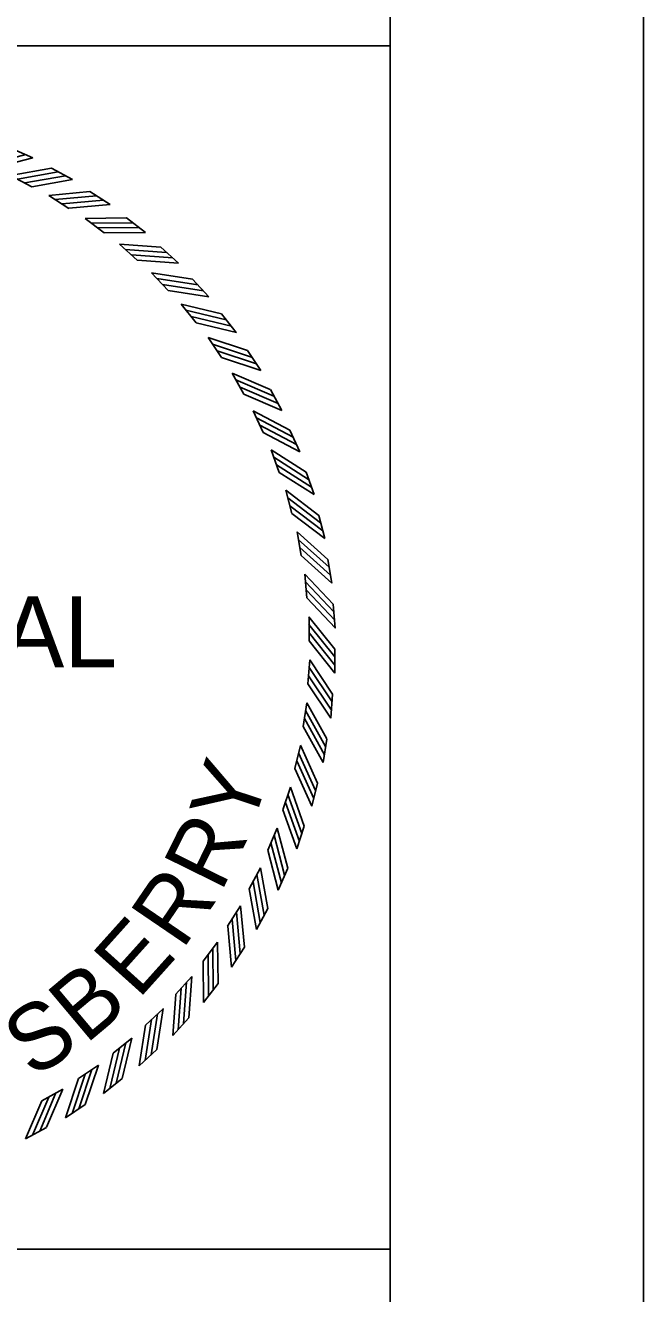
# Model space of a CAD drawing. Extents: x 0 to 1228740, y 0 to 152440.
# Drawn here: x 32.593 to 34, y 17.304 to 20.19 of the extents above; entities that cross this region are included whole.
import ezdxf

# ---------------------------------------------------------------- set-up
doc = ezdxf.new("R2010")
doc.units = 0
for name, color, linetype in [('R_Border', 7, 'Continuous'), ('R_No Plot', 7, 'Continuous'), ('STAMP_PP', 7, 'Continuous')]:
    doc.layers.add(name, color=color, linetype=linetype)

msp = doc.modelspace()

# ---------------------------------------------------------------- linework, layer by layer
at = {"layer": 'R_Border'}
for p, q in [((33.4231, 0.5768), (33.4231, 21.4232)), ((29.1131, 20.1432), (33.4231, 20.1432))]:
    msp.add_line(p, q, dxfattribs=at)
msp.add_lwpolyline([(33.9999, 22), (0, 22), (0, 0), (33.9999, 0)], close=True, dxfattribs=at)
at = {"layer": 'R_No Plot'}
for points in [[(33.4231, 17.4052), (33.4231, 0.5768), (1.516, 0.5768), (1.516, 21.4232), (20.2672, 21.4232), (20.2672, 20.4352), (28.7566, 20.4351), (28.7566, 20.0873), (29.1132, 20.0873), (29.1131, 20.1432), (30.6665, 20.1432)], [(30.6665, 20.1432), (30.6665, 17.4052), (33.4231, 17.4052)]]:
    msp.add_lwpolyline(points, dxfattribs=at)
msp.add_lwpolyline([(20.2672, 21.4232), (1.516, 21.4232), (1.516, 10.8708), (33.4231, 10.8708), (33.4231, 17.4052), (30.6665, 17.4052), (30.6665, 20.1432), (29.1132, 20.1432), (29.1132, 20.0873), (28.7566, 20.0873), (28.7566, 20.4351), (20.2672, 20.4351)], close=True, dxfattribs=at)
at = {"layer": 'STAMP_PP'}
for p, q in [((32.5606, 19.9103), (32.6107, 19.8889)), ((32.6526, 19.8648), (32.7006, 19.8393)), ((32.5598, 19.8484), (32.608, 19.8229)), ((32.6466, 19.8031), (32.6926, 19.7737)), ((32.7404, 19.8119), (32.7862, 19.7825)), ((32.7294, 19.7509), (32.7727, 19.7178)), ((32.8235, 19.7518), (32.8668, 19.7188)), ((32.8076, 19.692), (32.848, 19.6554)), ((32.9015, 19.6851), (32.9418, 19.6487)), ((32.8806, 19.6268), (32.9179, 19.587)), ((32.9736, 19.6123), (33.0108, 19.5726)), ((32.948, 19.5558), (32.9819, 19.5131)), ((33.0395, 19.5337), (33.0733, 19.491)), ((33.0093, 19.4796), (33.0396, 19.4342)), ((33.0987, 19.4499), (33.1288, 19.4046)), ((33.0641, 19.3985), (33.0905, 19.3507)), ((33.1507, 19.3615), (33.1771, 19.3139)), ((33.112, 19.3131), (33.1344, 19.2634)), ((33.1953, 19.2692), (33.2176, 19.2195)), ((33.1528, 19.2241), (33.1709, 19.1727)), ((33.2321, 19.1734), (33.2502, 19.1221)), ((33.186, 19.1321), (33.1998, 19.0793)), ((33.2608, 19.075), (33.2747, 19.0224)), ((33.2115, 19.0376), (33.2209, 18.9839)), ((33.2814, 18.9745), (33.2908, 18.9209)), ((33.2291, 18.9413), (33.2341, 18.887)), ((33.2936, 18.8727), (33.2985, 18.8185)), ((33.2387, 18.8439), (33.2392, 18.7893)), ((33.2973, 18.7702), (33.2978, 18.7158)), ((33.2402, 18.746), (33.2362, 18.6916)), ((33.2337, 18.6484), (33.2252, 18.5945)), ((33.2925, 18.6677), (33.2885, 18.6135)), ((33.2793, 18.566), (33.2708, 18.5123)), ((33.2191, 18.5516), (33.2062, 18.4986)), ((33.1965, 18.4563), (33.1793, 18.4046)), ((33.2577, 18.4657), (33.2449, 18.4129)), ((33.1662, 18.3633), (33.1447, 18.3131)), ((33.228, 18.3676), (33.2108, 18.316)), ((33.1283, 18.273), (33.1027, 18.2248)), ((33.1902, 18.2722), (33.1688, 18.2222)), ((33.083, 18.1863), (33.0536, 18.1403)), ((33.1447, 18.1803), (33.1192, 18.1323)), ((33.0308, 18.1035), (32.9977, 18.0601)), ((33.0917, 18.0925), (33.0624, 18.0467)), ((32.9719, 18.0253), (32.9353, 17.9849)), ((33.0317, 18.0093), (32.9987, 17.9661)), ((32.9067, 17.9523), (32.8669, 17.915)), ((32.965, 17.9314), (32.9286, 17.8911)), ((32.8357, 17.8849), (32.793, 17.851)), ((32.8922, 17.8593), (32.8525, 17.8221)), ((32.7595, 17.8236), (32.7141, 17.7933)), ((32.8136, 17.7934), (32.7709, 17.7596)), ((32.6784, 17.7688), (32.6306, 17.7424)), ((32.7298, 17.7342), (32.6845, 17.704)), ((32.6414, 17.6822), (32.5938, 17.6558))]:
    msp.add_line(p, q, dxfattribs=at)
for points in [[(32.5031, 19.8722), (32.5941, 19.8962)], [(32.5197, 19.8649), (32.6107, 19.8889)], [(32.5598, 19.8483), (32.6525, 19.8648)], [(32.5752, 19.84), (32.6679, 19.8565)], [(32.5921, 19.8315), (32.6848, 19.848)], [(32.608, 19.8229), (32.7007, 19.8394)], [(32.6466, 19.8031), (32.7403, 19.8119)], [(32.6612, 19.7935), (32.755, 19.8023)], [(32.6774, 19.7837), (32.7711, 19.7924)], [(32.6925, 19.7738), (32.7863, 19.7825)], [(32.7293, 19.7509), (32.8235, 19.7518)], [(32.7431, 19.7401), (32.8373, 19.7411)], [(32.7584, 19.729), (32.8526, 19.7299)], [(32.7727, 19.7179), (32.8669, 19.7188)], [(32.8075, 19.692), (32.9014, 19.6852)], [(32.8204, 19.6801), (32.9143, 19.6733)], [(32.8347, 19.6678), (32.9286, 19.6609)], [(32.848, 19.6555), (32.9419, 19.6487)], [(32.8805, 19.6268), (32.9735, 19.6123)], [(32.8924, 19.6139), (32.9854, 19.5994)], [(32.9056, 19.6004), (32.9986, 19.5859)], [(32.9179, 19.5871), (33.0109, 19.5726)], [(32.9479, 19.5559), (33.0394, 19.5337)], [(32.9587, 19.542), (33.0502, 19.5199)], [(32.9708, 19.5275), (33.0622, 19.5053)], [(32.9819, 19.5132), (33.0734, 19.491)], [(33.0092, 19.4796), (33.0986, 19.4499)], [(33.0188, 19.4649), (33.1082, 19.4353)], [(33.0296, 19.4494), (33.119, 19.4198)], [(33.0396, 19.4343), (33.1289, 19.4046)], [(33.064, 19.3985), (33.1506, 19.3616)], [(33.0724, 19.3831), (33.159, 19.3462)], [(33.0819, 19.3668), (33.1685, 19.3298)], [(33.0905, 19.3508), (33.1771, 19.3139)], [(33.112, 19.3132), (33.1952, 19.2692)], [(33.119, 19.2971), (33.2023, 19.2532)], [(33.1271, 19.2801), (33.2104, 19.2361)], [(33.1344, 19.2635), (33.2177, 19.2195)], [(33.1527, 19.2242), (33.232, 19.1735)], [(33.1584, 19.2076), (33.2377, 19.1569)], [(33.1651, 19.1899), (33.2444, 19.1392)], [(33.1709, 19.1728), (33.2503, 19.1221)], [(33.1859, 19.1321), (33.2608, 19.075)], [(33.1902, 19.1151), (33.2651, 19.0581)], [(33.1954, 19.097), (33.2703, 19.0399)], [(33.1999, 19.0794), (33.2747, 19.0223)], [(33.2114, 19.0376), (33.2813, 18.9746)], [(33.2143, 19.0203), (33.2842, 18.9573)], [(33.218, 19.0018), (33.2879, 18.9387)], [(33.221, 18.9839), (33.2909, 18.9209)], [(33.229, 18.9413), (33.2935, 18.8727)], [(33.2305, 18.9239), (33.2949, 18.8553)], [(33.2326, 18.9051), (33.2971, 18.8365)], [(33.2341, 18.887), (33.2986, 18.8184)], [(33.2386, 18.8439), (33.2972, 18.7702)], [(33.2386, 18.8264), (33.2972, 18.7527)], [(33.2392, 18.8075), (33.2978, 18.7338)], [(33.2392, 18.7894), (33.2978, 18.7157)], [(33.2402, 18.7461), (33.2925, 18.6678)], [(33.2378, 18.7098), (33.29, 18.6315)], [(33.2387, 18.7286), (33.291, 18.6503)], [(33.2363, 18.6917), (33.2885, 18.6134)], [(33.2336, 18.6484), (33.2793, 18.5661)], [(33.2307, 18.6312), (33.2764, 18.5488)], [(33.2252, 18.5945), (33.2709, 18.5122)], [(33.2282, 18.6124), (33.2739, 18.5301)], [(33.2147, 18.5347), (33.2534, 18.4489)], [(33.219, 18.5517), (33.2577, 18.4658)], [(33.2107, 18.5162), (33.2493, 18.4304)], [(33.2062, 18.4986), (33.2449, 18.4128)], [(33.1965, 18.4564), (33.228, 18.3677)], [(33.1852, 18.4218), (33.2167, 18.3331)], [(33.1908, 18.4398), (33.2223, 18.3511)], [(33.1793, 18.4046), (33.2108, 18.3159)], [(33.1662, 18.3634), (33.1902, 18.2723)], [(33.1521, 18.3298), (33.1761, 18.2388)], [(33.1591, 18.3473), (33.1832, 18.2563)], [(33.1448, 18.3132), (33.1688, 18.2222)], [(33.1282, 18.2731), (33.1447, 18.1804)], [(33.1199, 18.2577), (33.1364, 18.165)], [(33.1028, 18.2249), (33.1193, 18.1322)], [(33.1114, 18.2408), (33.1279, 18.1481)], [(33.083, 18.1863), (33.0917, 18.0926)], [(33.0636, 18.1555), (33.0723, 18.0618)], [(33.0734, 18.1717), (33.0822, 18.0779)], [(33.0537, 18.1404), (33.0624, 18.0466)], [(33.0308, 18.1036), (33.0317, 18.0094)], [(33.0089, 18.0745), (33.0098, 17.9803)], [(33.02, 18.0898), (33.021, 17.9956)], [(32.9977, 18.0602), (32.9987, 17.966)], [(32.96, 18.0125), (32.9532, 17.9186)], [(32.9719, 18.0254), (32.9651, 17.9315)], [(32.9354, 17.9849), (32.9286, 17.891)], [(32.9477, 17.9982), (32.9408, 17.9043)], [(32.8803, 17.9273), (32.8658, 17.8343)], [(32.8938, 17.9405), (32.8793, 17.8475)], [(32.9067, 17.9524), (32.8922, 17.8594)], [(32.867, 17.915), (32.8525, 17.822)], [(32.8219, 17.8742), (32.7998, 17.7827)], [(32.8358, 17.885), (32.8136, 17.7935)], [(32.7931, 17.851), (32.7709, 17.7595)], [(32.8074, 17.8621), (32.7852, 17.7706)], [(32.7448, 17.8141), (32.7152, 17.7247)], [(32.7595, 17.8237), (32.7298, 17.7343)], [(32.7142, 17.7933), (32.6845, 17.704)], [(32.7293, 17.8032), (32.6997, 17.7139)], [(32.6467, 17.751), (32.6097, 17.6644)], [(32.663, 17.7605), (32.6261, 17.6739)], [(32.6784, 17.7688), (32.6415, 17.6823)], [(32.6307, 17.7424), (32.5938, 17.6558)]]:
    msp.add_lwpolyline(points, dxfattribs=at)

# ---------------------------------------------------------------- texts
msp.add_text('PROFESSIONAL', height=0.161547, dxfattribs=at).set_placement((31.1214, 18.7292))
for s, rotation, p in [('Y', 71.7733, (33.1072, 18.3567)), ('R', 63.7477, (33.0384, 18.2148)), ('R', 55.7221, (32.9504, 18.084)), ('E', 48.0613, (32.8502, 17.9717)), ('B', 40.0357, (32.7301, 17.8695)), ('S', 32.7397, (32.6095, 17.7919))]:
    msp.add_text(s, height=0.1503, rotation=rotation, dxfattribs=at).set_placement(p)

doc.saveas('drawing.dxf')
